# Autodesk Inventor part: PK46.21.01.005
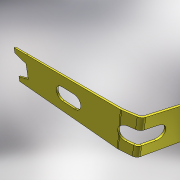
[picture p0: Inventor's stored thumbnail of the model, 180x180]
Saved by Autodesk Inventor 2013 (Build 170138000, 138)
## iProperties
Created: 2005-04
Part Number: PK46.21.01.005
Material: Steel, Mild
Document SubType Name: Sheet Metal
Designer: salex
Manufacturer: Standard
Standards Organization: Custom
Density: 7.86 g/cm^3
Sheet Metal Rule: Default
Author: salex
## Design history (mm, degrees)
node "ФлнОтгиб1"
  sketch "Эскиз1"
    geometry: L1 (2.831, 0)-(583.165, 0); L2 (583.165, 0)-(658.074, 12.834); L3 (658.074, 12.834)-(731.169, 207.98); L4 (658.074, 12.834)-(664.495, -24.645); L5 (646.711, 10.887)-(404.321, -30.641); L6 (731.169, 207.98)-(754.432, 72.205)
    constraints: 12 end point, 3 perpendicular, 1 horizontal, 1 point on line, 1 other
    dimensions: "d20" = 76 distance of L1.end L2.end; "d21" = 180 distance from line of L3.end L2; "d22" = 105 distance from line of L3.end L4; "d23" = 98 distance from line of L1.start L2; "d24" = 753 distance from line of L1.start L6
sketch "Sketch2"
  geometry: L1 (330, 140)-(250, 140); L2 (250, 60)-(330, 60); L3 (578.633, 0)-(0, 0) reference; L4 (578.633, 200)-(0, 200) reference; L5 (0, 0)-(0, 200) reference; L6 (-106.367, 199.918)-(-106.367, 169.918); L7 (-106.367, 169.918)-(-16.367, 144.959); L8 (-16.367, 54.959)-(-106.367, 30); L9 (-106.367, 30)-(-106.367, 0); L10 (-16.367, 54.959)-(-16.367, 144.959); L11 (578.633, 0)-(578.633, 200) reference; L12 (0, 0)-(-106.367, 0); L13 (0, 200)-(-106.367, 199.918); A1 r 40 centre (330, 100) between (330, 60) and (330, 140); A2 r 40 centre (250, 100) between (250, 140) and (250, 60); 1 further point
  constraints: 18 end point, 4 point on circle, 4 tangent, 2 centre point, 2 equal length, 1 collinear, 1 horizontal, 1 parallel, 1 perpendicular, 1 point on line, 1 vertical
  dimensions: "d25" = 80 distance of A1.centre A2.centre; "d26" = 40 radius of A2; "d27" = 200 distance between parallel lines of L3 L4 (derived); "d28" = 100 distance from line of A2.centre L4 (= 0.5 x d27); "d29" = 250 distance from line of A2.centre L5; "d32" = 30 distance of L8.end L9.end; "d33" = 90 distance of L8.start L7.end; "d34" = 90 distance between parallel lines of L6 L10; "d35" = 105.5 deg angle of L10 L8; "d37" = 685 distance between parallel lines of L9 L11
cut "Cut1" dims "d30" = 10 (= Thickness), "d31" = 0
node "Face1"
sketch "Sketch3"
  geometry: L1 (30.937, 60)-(150.937, 60); L2 (150.937, 140)-(30.937, 140); L3 (187.937, 0)-(187.937, 200) reference; L4 (187.937, 0)-(88.725, 0) reference; A1 r 40 centre (30.937, 100) between (30.937, 140) and (30.937, 60); A2 r 40 centre (150.937, 100) between (150.937, 60) and (150.937, 140); 1 further point
  constraints: 4 end point, 4 point on circle, 4 tangent, 2 centre point, 1 horizontal, 1 parallel
  dimensions: "d43" = 120 distance of A2.centre A1.centre; "d44" = 40 radius of A1; "d45" = 200 distance of L3.start L3.end (derived); "d46" = 100 distance from line of A2.centre L4 (= 0.5 x d45); "d47" = 37 distance from line of A2.centre L3
cut "Cut2" sketch "Sketch3" dims "d48" = 10 (= Thickness), "d49" = 0
body "Solid1"
face "Плакирование1" dims "d13" = 200, "d14" = 10 (= BendReliefWidth), "d16" = 20 (= MinimumRemnant), "d18" = 20 (= BendRadius), "d19" = 10, "Thickness" = 10
bend "Изгиб1" dims "d14" = 10 (= BendReliefWidth), "d15" = 5 (= BendReliefDepth), "d16" = 20 (= MinimumRemnant), "d17" = 20 (= BendRadius), "d18" = 20 (= BendRadius), "d19" = 10, "SeamGap" = 0.01, "Thickness" = 10
face "Plate2" dims "d38" = 20 (= BendRadius), "d39" = 10 (= BendReliefWidth), "d41" = 20 (= MinimumRemnant), "Thickness" = 10
bend "Bend2" dims "d38" = 20 (= BendRadius), "d39" = 10 (= BendReliefWidth), "d40" = 5 (= BendReliefDepth), "d41" = 20 (= MinimumRemnant), "d42" = 20 (= BendRadius), "SeamGap" = 0.01, "Thickness" = 10
other parameters: "BendRadius" = 20, "BendReliefDepth" = 5 (= 0.5 x Thickness)
